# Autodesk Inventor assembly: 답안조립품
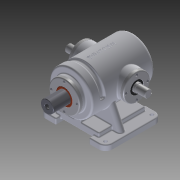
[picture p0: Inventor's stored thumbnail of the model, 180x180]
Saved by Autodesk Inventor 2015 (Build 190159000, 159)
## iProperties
Created: 2015-10
Part Number: 답안조립품
Document SubType Name: Assembly
Designer: youjin06
Mass: 9437.33 g
Surface Area: 4327.28 cm^2
Volume: 2315.26 cm^3
Density: 4.07615 g/cm^3
Author: youjin06
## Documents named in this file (13)
- C:\Users\youjin06\Desktop\351019V1012\답안조립품.iam
- C:\Users\youjin06\Desktop\351019V1012\본체.ipt
- C:\Users\youjin06\Desktop\351019V1012\슬라이드 커버.ipt
- C:\Users\youjin06\Desktop\351019V1012\부시.ipt
- C:\Users\youjin06\Desktop\351019V1012\베어링 6205.ipt
- 베어링 6205.ipt
- C:\Users\youjin06\Desktop\351019V1012\편심축.ipt
- C:\Users\youjin06\Desktop\351019V1012\축 커버.ipt
- C:\Users\youjin06\Desktop\351019V1012\스프링.ipt
- C:\Users\youjin06\Desktop\351019V1012\M4x0.7.ipt
- C:\Users\youjin06\Desktop\351019V1012\슬라이드.ipt
- C:\Users\youjin06\Desktop\351019V1012\오일실.ipt
- 오일실.ipt
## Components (12 placed, 1 different names)
1. M4x0.7:1 — Insert:1
2. M4x0.7:4
3. M4x0.7:5
4. M4x0.7:6
5. M4x0.7:3 — Insert:2
6. M4x0.7:7
7. M4x0.7:8
8. M4x0.7:9
9. M4x0.7:2 — Insert:3
10. M4x0.7:10
11. M4x0.7:11
12. M4x0.7:12
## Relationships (3: Insert 3)
- Insert:1: M4x0.7:1
- Insert:2: M4x0.7:3
- Insert:3: M4x0.7:2
